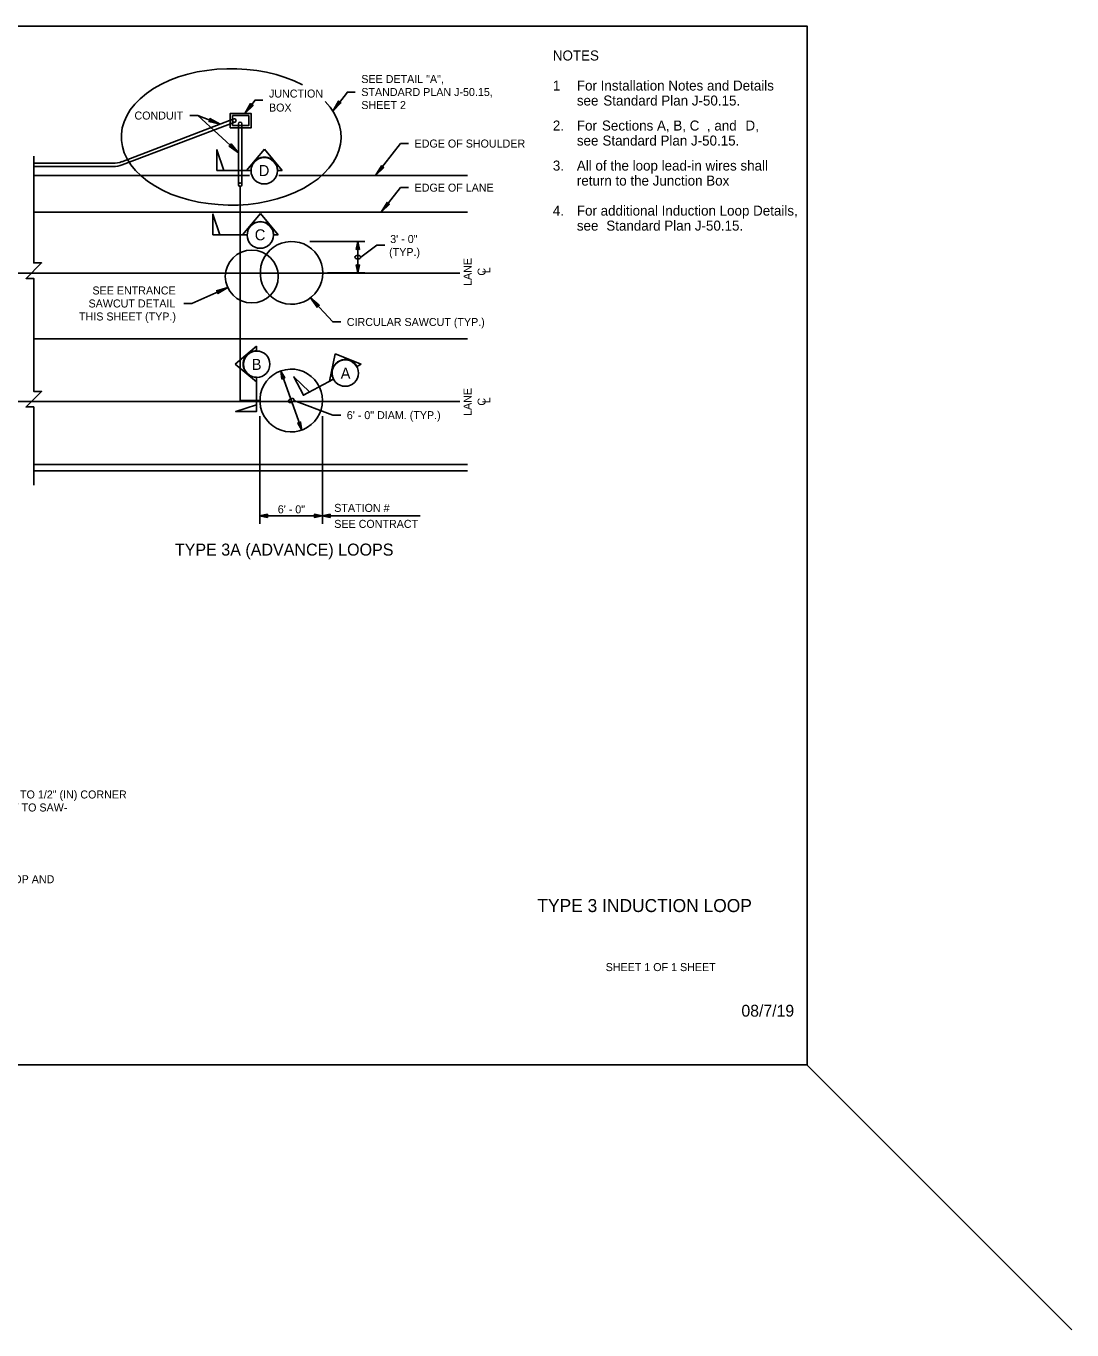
# Model space of a CAD drawing. Extents: x 99862 to 103680, y 99470 to 102076.
# Drawn here: x 101589 to 103680, y 99470 to 102076 of the extents above; entities that cross this region are included whole.
import ezdxf

# ---------------------------------------------------------------- set-up
doc = ezdxf.new("R2010")
doc.units = 0
for name, color, linetype in [('Level 1', 7, 'Continuous'), ('Level 15', 7, 'Continuous'), ('Level 18', 7, 'Continuous'), ('Level 2', 7, 'Continuous'), ('Level 20', 7, 'Continuous'), ('Level 22', 7, 'Continuous'), ('Level 27', 7, 'Continuous'), ('Level 60', 7, 'Continuous'), ('Level 62', 7, 'Continuous'), ('Level 9', 7, 'Continuous')]:
    doc.layers.add(name, color=color, linetype=linetype)

msp = doc.modelspace()

# ---------------------------------------------------------------- linework, layer by layer
at = {"layer": 'Level 1'}
msp.add_line((103150, 100000), (103680.3, 99469.7), dxfattribs=at)
msp.add_lwpolyline([(99862, 99999.5), (103151, 99999.5), (103151, 102075.5), (99862, 102075.5)], close=True, dxfattribs=at)
at = {"layer": 'Level 15'}
for p, q in [((101916.9, 101896.7), (101932.9, 101896.7)), ((101977.2, 101879.5), (101932.9, 101896.7)), ((102014.3, 101822.3), (101932.9, 101896.7)), ((102258.8, 101613.7), (102290.4, 101637.9)), ((102306.4, 101637.9), (102290.4, 101637.9)), ((102456.6, 101581.7), (101340.8, 101581.7)), ((101992.6, 101553.1), (101921.1, 101521.1)), ((101905.1, 101521.1), (101921.1, 101521.1)), ((102456.6, 101325.1), (101341.3, 101325.1))]:
    msp.add_line(p, q, dxfattribs=at)
for points in [[(102247.7, 101943.7), (102232, 101943.7), (102202.6, 101905.7)], [(102063.1, 101927.6), (102047.4, 101927.6), (102027.3, 101901.6)], [(102354.2, 101840.7), (102338.2, 101840.7), (102288, 101776.6)], [(101605, 101815.8), (101605, 101602.1), (101620.5, 101602.1), (101589.5, 101571.1), (101605, 101571.1), (101605, 101432.6)], [(102354.2, 101752.6), (102338.2, 101752.6), (102299.6, 101703.4)], [(102156.8, 101645), (102266.8, 101645)], [(102252.8, 101645), (102252.8, 101582.5)], [(102191.8, 101582.6), (102266.8, 101582.6)], [(102218.7, 101484.1), (102202.7, 101484.1), (102158, 101532.5)], [(101605, 101432.6), (101605, 101345.5), (101620.5, 101345.5), (101589.5, 101314.5), (101605, 101314.5), (101605, 101157.8)], [(102140.6, 101268.3), (102098.5, 101386.1)], [(102218.7, 101297.9), (102202.7, 101297.9), (102125, 101327.4)], [(102057, 101295.6), (102057, 101080.6)], [(102182.1, 101295.6), (102182.1, 101080.6)], [(102056.4, 101096.6), (102181.6, 101096.6)], [(102181.6, 101096.6), (102377.6, 101096.6)]]:
    msp.add_lwpolyline(points, dxfattribs=at)
for points in [[(102026.8, 101900.9), (102038.4, 101920.7), (102040.2, 101918.1), (102043.2, 101917.1)], [(102202.6, 101905.7), (102218.9, 101921.9), (102215.9, 101922.9), (102214.2, 101925.6)], [(101977.2, 101879.5), (101954.9, 101885), (101956.9, 101887.4), (101957, 101890.6)], [(102014.3, 101822.3), (101995.5, 101835.5), (101998.3, 101837), (101999.5, 101839.9)], [(102288, 101776.6), (102299.8, 101796.5), (102301.5, 101793.8), (102304.5, 101792.8)], [(102299.6, 101703.4), (102311.3, 101723.2), (102313, 101720.5), (102316, 101719.5)], [(102252.8, 101645), (102249.7, 101629.2), (102252.8, 101630), (102255.8, 101629.2)], [(102252.8, 101582.5), (102249.7, 101598.3), (102252.8, 101597.5), (102255.8, 101598.3)], [(101992.6, 101553.1), (101973, 101541), (101972.7, 101544.2), (101970.5, 101546.5)], [(102158, 101532.5), (102171.3, 101513.7), (102172.8, 101516.5), (102175.7, 101517.7)], [(102098.5, 101385.9), (102106.7, 101372.2), (102103.6, 101371.8), (102100.9, 101370.1)], [(102140.7, 101268.1), (102138.3, 101284), (102135.7, 101282.3), (102132.5, 101281.9)], [(102181.6, 101096.6), (102197.3, 101093.5), (102196.6, 101096.6), (102197.3, 101099.7)]]:
    msp.add_lwpolyline(points, close=True, dxfattribs=at)
msp.add_circle((102040.7, 101575), 52.9, dxfattribs=at)
msp.add_ellipse((101999.5, 101854), major_axis=(-219.6, 0), ratio=0.621053, start_param=4.006009, end_param=9.970943, dxfattribs=at)
for centre, major_axis in [((102252.8, 101613.7), (6, 0)), ((102119.5, 101327.2), (5.59, 2.17))]:
    msp.add_ellipse(centre, major_axis=major_axis, ratio=0.57735, dxfattribs=at)
at = {"layer": 'Level 18'}
msp.add_lwpolyline([(102002.3, 101876.5), (102034.7, 101876.5), (102034.7, 101896.5), (102002.3, 101896.5), (102002.3, 101876.5)], dxfattribs=at)
for centre in [(102005.9, 101886.8), (102017.5, 101880), (102017.5, 101758.4)]:
    msp.add_circle(centre, 3.5, dxfattribs=at)
at = {"layer": 'Level 2'}
for p, q in [((102017.3, 101582), (102057.4, 101582)), ((102017.3, 101327.1), (102055.2, 101327.1))]:
    msp.add_line(p, q, dxfattribs=at)
at = {"layer": 'Level 20'}
for p, q in [((102014.1, 101880.2), (102014, 101758.4)), ((102021.1, 101880.3), (102021, 101758.4)), ((101605, 101450.5), (102472, 101450.5)), ((101605, 101199.1), (102472, 101199.1))]:
    msp.add_line(p, q, dxfattribs=at)
for points in [[(101997.8, 101872), (102039.2, 101872), (102039.2, 101901), (101997.8, 101901), (101997.8, 101872)], [(101605, 101776.9), (102036, 101776.9)], [(102094.6, 101776.9), (102472, 101776.9)], [(101605, 101703.4), (102089.1, 101703.4)], [(102089.1, 101703.4), (102472, 101703.4)], [(102182.1, 101295.8), (102182.1, 101295.2)]]:
    msp.add_lwpolyline(points, dxfattribs=at)
for points in [[(102056.4, 101096.6), (102072.1, 101093.5), (102071.4, 101096.6), (102072.1, 101099.7)], [(102181.6, 101096.6), (102165.8, 101099.7), (102166.6, 101096.6), (102165.8, 101093.5)]]:
    msp.add_lwpolyline(points, close=True, dxfattribs=at)
at = {"layer": 'Level 22'}
for points in [[(102017.3, 101327.1), (102017.3, 101754.7)], [(102182.7, 101582.3), (102182, 101591.3), (102179.9, 101600.4), (102176.8, 101608.7), (102172.3, 101616.7), (102166.7, 101624.1), (102160.1, 101630.3), (102152.8, 101635.9), (102144.8, 101640.1), (102136.1, 101642.9), (102127.1, 101644.6), (102118.1, 101645), (102108.7, 101643.9), (102100, 101641.5), (102091.6, 101638), (102083.6, 101633.1), (102076.7, 101627.5), (102070.8, 101620.6), (102065.6, 101612.9), (102061.7, 101604.6), (102059, 101595.8), (102057.9, 101586.8), (102057.9, 101577.7), (102059, 101568.7), (102061.7, 101560), (102065.6, 101551.6), (102070.8, 101543.9), (102076.7, 101537), (102083.6, 101531.4), (102091.6, 101526.5), (102100, 101523), (102108.7, 101520.6), (102118.1, 101519.6), (102127.1, 101519.9), (102136.1, 101521.7), (102144.8, 101524.4), (102152.8, 101528.6), (102160.1, 101534.2), (102166.7, 101540.5), (102172.3, 101547.8), (102176.8, 101555.8), (102179.9, 101564.1), (102182, 101573.2), (102182.7, 101582.3)], [(102182.1, 101327.2), (102181.4, 101336.2), (102179.3, 101345.3), (102176.2, 101353.7), (102171.7, 101361.7), (102166.1, 101369), (102159.5, 101375.3), (102152.2, 101380.8), (102144.2, 101385), (102135.5, 101387.8), (102126.5, 101389.5), (102117.5, 101389.9), (102108.1, 101388.8), (102099.4, 101386.4), (102091, 101382.9), (102083, 101378), (102076.1, 101372.5), (102070.2, 101365.5), (102065, 101357.8), (102061.1, 101349.5), (102058.4, 101340.8), (102057.3, 101331.7), (102057.3, 101322.7), (102058.4, 101313.6), (102061.1, 101304.9), (102065, 101296.5), (102070.2, 101288.9), (102076.1, 101281.9), (102083, 101276.3), (102091, 101271.5), (102099.4, 101268), (102108.1, 101265.5), (102117.5, 101264.5), (102126.5, 101264.8), (102135.5, 101266.6), (102144.2, 101269.4), (102152.2, 101273.6), (102159.5, 101279.1), (102166.1, 101285.4), (102171.7, 101292.7), (102176.2, 101300.7), (102179.3, 101309.1), (102181.4, 101318.1), (102182.1, 101327.2)]]:
    msp.add_lwpolyline(points, dxfattribs=at)
at = {"layer": 'Level 27'}
for p, q in [((101781, 101804.5), (102004.8, 101890.4)), ((101781.8, 101798), (102007.1, 101883.5)), ((101605, 101186.4), (102472, 101186.4))]:
    msp.add_line(p, q, dxfattribs=at)
for points in [[(101605, 101801.2), (101763.1, 101801.2)], [(101605, 101794.7), (101763.9, 101794.7)]]:
    msp.add_lwpolyline(points, dxfattribs=at)
for centre in [(101763.1, 101851.2), (101763.9, 101844.7)]:
    msp.add_arc(centre, 50, 270, 291.0084, dxfattribs=at)
at = {"layer": 'Level 60'}
msp.add_line((103151, 102075.5), (103151, 102075.5), dxfattribs=at)
at = {"layer": 'Level 9'}
for p, q in [((102065.9, 101829.6), (102030.2, 101787)), ((102101.6, 101787), (102065.9, 101829.6)), ((102039.1, 101786.7), (101971.2, 101786.7)), ((102030.2, 101787), (102039.5, 101787)), ((102092.3, 101787), (102101.6, 101787)), ((102017.3, 101752.7), (102017.3, 101730.4)), ((102058, 101701.1), (102022.3, 101658.4)), ((102093.7, 101658.4), (102058, 101701.1)), ((102031.2, 101658.2), (101963.3, 101658.2)), ((102022.3, 101658.4), (102031.6, 101658.4)), ((102084.4, 101658.4), (102093.7, 101658.4)), ((102050, 101435.7), (102007.3, 101400.1)), ((102050, 101426.4), (102050, 101435.7)), ((102207.5, 101420.2), (102196.1, 101365.8)), ((102259.1, 101399.5), (102207.5, 101420.2)), ((102007.3, 101400.1), (102049.9, 101364.3)), ((102250.9, 101395.1), (102259.1, 101399.5)), ((102049.9, 101364.3), (102049.9, 101373.6)), ((102050.2, 101373.2), (102050.1, 101305.3)), ((102204.1, 101369.8), (102144.2, 101337.7)), ((102196.1, 101365.8), (102204.3, 101370.2))]:
    msp.add_line(p, q, dxfattribs=at)
for points in [[(101984.7, 101787), (101971, 101828.2), (101971, 101787)], [(101976.7, 101658.4), (101963.1, 101699.7), (101963.1, 101658.4)], [(102156, 101344.3), (102124.5, 101374.2), (102144, 101337.8)], [(102049.9, 101318.8), (102008.6, 101305.2), (102049.9, 101305.1)]]:
    msp.add_lwpolyline(points, close=True, dxfattribs=at)
for centre in [(102065.6, 101786.4), (102057.7, 101657.8), (102050.6, 101399.7), (102227.6, 101382)]:
    msp.add_circle(centre, 26.4, dxfattribs=at)
for centre, start, end in [((102065.9, 101787), 359.9978, 180.0022), ((102058, 101658.4), 359.9978, 180.0022), ((102050, 101400), 89.9264, 269.9308), ((102227.6, 101382.7), 28.1948, 208.1993)]:
    msp.add_arc(centre, 26.4, start, end, dxfattribs=at)

# ---------------------------------------------------------------- texts
at = {"layer": 'Level 15'}
msp.add_text('08/7/19', height=23.62, dxfattribs=at).set_placement((103019.6, 100095.8))
at = {"layer": 'Level 18'}
for s, p in [('STATION #', (102205.6, 101104.6)), ('SEE CONTRACT', (102205.6, 101072.6))]:
    msp.add_text(s, height=16, rotation=360, dxfattribs=at).set_placement(p)
at = {"layer": 'Level 20'}
for s, height, p in [('NOTES', 20, (102642.6, 102006.7)), ('1', 20, (102642.6, 101946.7)), ('For Installation Notes and Details ', 20, (102690.6, 101946.7)), ('JUNCTION ', 16, (102075.1, 101932.6)), ('BOX', 16, (102075.1, 101904.6)), ('see ', 20, (102690.6, 101916.7)), ('Standard Plan J-50.15.', 20, (102743.5, 101916.7)), ('CONDUIT', 16, (101806.2, 101888.7)), ('2.', 20, (102642.6, 101866.7)), ('For ', 20, (102690.6, 101866.7)), ('Sections A, B, C', 20, (102740.8, 101866.7)), (', and ', 20, (102950.6, 101866.7)), ('D', 20, (103027.7, 101866.7)), (',', 20, (103047.3, 101866.7)), ('EDGE OF SHOULDER', 16, (102366.2, 101832.7)), ('see', 20, (102690.6, 101836.7)), (' Standard Plan J-50.15.', 20, (102734.4, 101836.7)), ('D', 22, (102054.6, 101775.8)), ('3.', 20, (102642.6, 101786.7)), ('All of the loop lead-in wires shall ', 20, (102690.6, 101786.7)), ('EDGE OF LANE', 16, (102366.2, 101744.6)), ('return to the Junction Box', 20, (102690.6, 101756.7)), ('4.', 20, (102642.6, 101696.7)), ('For additional Induction Loop Details,', 20, (102690.6, 101696.7)), ('see ', 20, (102690.6, 101666.7)), ('Standard Plan J-50.15.', 20, (102749.5, 101666.7)), ('C', 22, (102046.7, 101647.3)), ('SEE ENTRANCE', 16, (101722.2, 101539.1)), ('SAWCUT DETAIL', 16, (101714.4, 101513.1)), ('THIS SHEET (TYP.)', 16, (101695.4, 101487.1)), ('CIRCULAR SAWCUT (TYP.)', 16, (102230.7, 101476.1)), ('A', 22, (102218.4, 101370.6)), ('6\' - 0" DIAM. (TYP.)', 16, (102230.7, 101289.9)), ('6\' - 0"', 16, (102092.7, 101101.7)), ('TYPE 3A (ADVANCE) LOOPS', 24, (101887, 101017.2)), ('CHISEL OUT 1/8" (IN) TO 1/2" (IN) CORNER', 16, (101358.2, 100531.8)), ('REMOVE PAVEMENT TO SAW-', 16, (101358.2, 100505.8)), ('CENTER OF LOOP AND', 16, (101405.9, 100362.4))]:
    msp.add_text(s, height=height, dxfattribs=at).set_placement(p)
for s, height, rotation, p in [('SEE DETAIL "A",', 16, 360, (102259.7, 101961.7)), ('STANDARD PLAN J-50.15,', 16, 360, (102259.7, 101935.7)), ('SHEET 2 ', 16, 360, (102259.7, 101909.7)), ('3\' - 0"', 16, 360, (102317.5, 101641.9)), ('(TYP.)', 16, 360, (102315.3, 101615.9)), ('LANE', 16, 90, (102480, 101556.1)), ('C', 16, 90, (102508.2, 101576.7)), ('L', 16, 90, (102517.6, 101581.6)), ('B', 22, 359.8763, (102040.5, 101388.3)), ('LANE', 16, 90, (102480, 101296.4)), ('C', 16, 90, (102508.2, 101316.9)), ('L', 16, 90, (102517.6, 101321.9))]:
    msp.add_text(s, height=height, rotation=rotation, dxfattribs=at).set_placement(p)
at = {"layer": 'Level 62'}
for s, height, p in [('TYPE 3 INDUCTION LOOP', 26, (102611.6, 100304.8)), ('SHEET 1 OF 1 SHEET', 16, (102748.2, 100186.8))]:
    msp.add_text(s, height=height, dxfattribs=at).set_placement(p)

doc.saveas('drawing.dxf')
